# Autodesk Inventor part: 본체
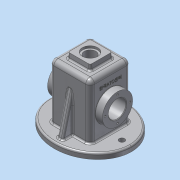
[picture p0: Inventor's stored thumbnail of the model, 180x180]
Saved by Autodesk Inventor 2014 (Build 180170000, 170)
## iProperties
Created: 2017-07
Part Number: 본체
Material: 알루미늄 6061
Document SubType Name: Modeling
Designer: 702-11
Density: 2.71 g/cm^3
Appearance: 알루미늄 - 평지
Mass: 947.78 g
Surface Area: 978.952 cm^2
Volume: 349.734 cm^3
Author: 702-11
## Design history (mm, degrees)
sketch "스케치1"
  geometry: L1 (0, 65)-(0, 0); L2 (0, 0)-(75, 0); 1 further point; 1 other entity
  constraints: 4 end point, 1 coincident, 1 horizontal, 1 vertical, 4 other
  dimensions: "d0" = 75 distance of L1.end L2.end; "d1" = 65 distance of L1.start L1.end
extrude "돌출1" new body sketch "스케치1" distance "d2" = 10; taper "d3" = 0 deg
sketch "스케치2"
  geometry: L1 (-37, -37)-(37, -37); L2 (37, -37)-(37, 37); L3 (37, 37)-(-37, 37); L4 (-37, 37)-(-37, -37); L5 (-37, -37)-(37, 37); L6 (37, -37)-(-37, 37); 1 further point; 1 other entity
  constraints: 12 end point, 2 midpoint, 2 parallel, 2 perpendicular, 1 horizontal, 1 other
  dimensions: "d4" = 74 distance of L3.end L1.start
extrude "돌출2" join sketch "스케치2" distance "d5" = 100; taper "d6" = 0 deg
sketch "스케치3"
  geometry: L1 (-32, -32)-(32, -32); L2 (32, -32)-(32, 32); L3 (32, 32)-(-32, 32); L4 (-32, 32)-(-32, -32); L5 (-32, -32)-(32, 32); L6 (32, -32)-(-32, 32); 1 further point; 1 other entity
  constraints: 12 end point, 2 midpoint, 2 parallel, 2 perpendicular, 1 horizontal, 1 other
  dimensions: "d7" = 64 distance of L1.end L2.end
extrude "돌출3" cut sketch "스케치3" distance "d8" = 100; taper "d9" = 0 deg
sketch "스케치4"
  geometry: L1 (-20, -20)-(20, -20); L2 (20, -20)-(20, 20); L3 (20, 20)-(-20, 20); L4 (-20, 20)-(-20, -20); L5 (-20, -20)-(20, 20); L6 (20, -20)-(-20, 20); 1 further point
  constraints: 12 end point, 2 midpoint, 2 parallel, 2 perpendicular, 1 horizontal
  dimensions: "d10" = 40 distance of L3.end L1.start
extrude "돌출4" join sketch "스케치4" distance "d11" = 10; taper "d12" = 0 deg
sketch "스케치5"
  geometry: L1 (-75, 0)-(-75, 10) reference; L2 (-75, 10)-(-37, 10) reference; L3 (-37, 10)-(-37, 110) reference; L4 (-37, 110)-(-20, 110) reference; L5 (-20, 110)-(-20, 120) reference; L6 (-20, 120)-(20, 120) reference; L7 (20, 120)-(20, 110) reference; L8 (20, 110)-(37, 110) reference; L9 (37, 110)-(37, 10) reference; L10 (37, 10)-(75, 10) reference; L11 (75, 10)-(75, 0) reference; L12 (75, 0)-(32, 0) reference; L13 (32, 0)-(32, 100) reference; L14 (32, 100)-(-32, 100) reference; L15 (-32, 100)-(-32, 0) reference; L16 (-32, 0)-(-75, 0) reference; L17 (-37, 55)-(37, 55); L18 (-37, 55)-(-50, 55); L19 (-50, 55)-(-50, 82.5); L20 (-50, 82.5)-(-37, 82.5); L21 (-37, 82.5)-(-37, 55); L22 (37, 55)-(50, 55); L23 (50, 55)-(50, 82.5); L24 (50, 82.5)-(37, 82.5); L25 (37, 82.5)-(37, 55); L26 (-37, 82.5)-(-32, 82.5); L27 (37, 82.5)-(32, 82.5); L28 (-25, 75.5)-(-25, 55); L29 (32, 82.5)-(25, 75.5); L30 (25, 75.5)-(25, 55); L31 (-25, 75.5)-(-32, 82.5); L32 (-32, 82.5)-(-32, 55); L33 (32, 82.5)-(32, 55); L34 (32, 0)-(32, 100) reference; 1 further point
  constraints: 34 end point, 10 point on line, 7 perpendicular, 5 parallel, 2 horizontal
  dimensions: "d13" = 55 distance between parallel lines of L12 L17; "d14" = 100 distance between parallel lines of L19 L23; "d15" = 13 distance of L23.end L24.end; "d16" = 55 diameter of L24 L17; "d18" = 55 diameter of L20 L17; "d19" = 7 distance between parallel lines of L15 L28; "d20" = 7 distance between parallel lines of L13 L30; "d21" = 135 deg angle of L13 L29; "d23" = 135 deg angle of L15 L31; "d24" = 55 diameter of L26.end L17 (derived); "d25" = 55 diameter of L27.end L17 (derived)
revolve "회전1" sketch "스케치5" stored, may be unused: angle "d26" = 90 deg
hole "구멍1" diameter "d29" = 32; stored, may be unused: countersink angle "d33" = 90 deg, drill point angle "d35" = 118 deg; dims "d27" = 10, "d28" = 10, "d30" = 6, "d31" = 4, "d32" = 2, "d34" = 8
sketch "스케치6"
  geometry: L1 (65, 10)-(65, 0) reference; L2 (65, 0)-(32, 0) reference; L3 (32, 0)-(32, 100) reference; L4 (32, 100)-(-32, 100) reference; L5 (-32, 100)-(-32, 0) reference; L6 (-32, 0)-(-65, 0) reference; L7 (-65, 0)-(-65, 10) reference; L8 (-65, 10)-(-37, 10) reference; L9 (-37, 10)-(-37, 110) reference; L10 (-37, 110)-(-20, 110) reference; L11 (-20, 110)-(-20, 120) reference; L12 (-20, 120)-(20, 120) reference; L13 (20, 120)-(20, 110) reference; L14 (20, 110)-(37, 110) reference; L15 (37, 110)-(37, 10) reference; L16 (37, 10)-(65, 10) reference; L17 (-55, 10)-(-37, 82.194); 1 further point
  constraints: 2 end point, 2 point on line
  dimensions: "d36" = 10 distance of L7.end L17.start; "d37" = 14 deg angle of L7 L17
feature "리브1" sketch "스케치6" dims "d38" = 1, "d39" = 10, "d40" = 0, "d41" = 0, "d42" = 1, "d43" = 1
sketch "스케치7"
  geometry: 2 further points
  constraints: 1 coincident
hole "구멍2" sketch "스케치7" at (0, 0) diameter "d44" = 21; stored, may be unused: countersink angle "d48" = 90 deg, drill point angle "d50" = 118 deg; dims "d45" = 6, "d46" = 28, "d47" = 4, "d49" = 8
sketch "스케치8"
  geometry: 2 further points; 1 other entity
  constraints: 1 horizontal alignment, 1 other
  dimensions: "d51" = 58 distance of point (0, 0) point (-58, 0)
hole "구멍3" sketch "스케치8" at (-58, 0) diameter "d52" = 10; stored, may be unused: countersink angle "d56" = 90 deg, drill point angle "d58" = 118 deg; dims "d53" = 6, "d54" = 28, "d55" = 4, "d57" = 8
sketch "스케치9" dims "d59" = 45
  geometry: C1 r 16 at (0, 0) reference; 3 further points
  constraints: 2 horizontal alignment, 1 coincident, 2 other
hole "구멍4" sketch "스케치9" at (22.5, 0) diameter "d60" = 3.242; stored, may be unused: countersink angle "d64" = 90 deg, drill point angle "d66" = 118 deg; dims "d61" = 8, "d62" = 28, "d63" = 4, "d65" = 10
fillet "모깎기1" dims "d71" = 3
fillet "모깎기2" dims "d72" = 8
fillet "모깎기7" dims "d85" = 3
fillet "모깎기3" dims "d73" = 8
feature "면 기울기2" dims angle "d81" = 5 deg
fillet "모깎기4" dims "d74" = 3
fillet "모깎기5" dims "d75" = 0.5
sketch "스케치10"
  geometry: L1 (-18, 12)-(-18, 46) reference; L2 (92, 66)-(0, 66) reference; 3 further points
  constraints: 1 other
  dimensions: "d77" = 30 distance from line of L1 point (12, 29); "d78" = 37 distance from line of L2 point (12, 29)
feature "엠보싱1" sketch "스케치10" dims "d0" = 75, "d1" = 65, "d7" = 64, "d79" = 0.5, "d80" = 0
chamfer "모따기1" distance "d82" = 1; stored, may be unused: second distance "d83" = 2, angle "d84" = 45 deg
node "솔리드1"
mirror "대칭1"
pattern_circular "원형 패턴1" dims angle "d68" = 360 deg
mirror "대칭2"
node "절단 모서리 투영1"
node "절단 모서리 투영2"
